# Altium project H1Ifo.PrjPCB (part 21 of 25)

## Sheet IfoEndY2.SchDoc: D1800185
size C; Engineer: Daniel Sigg; DocumentNumber: 6; Revision: 4; SheetNumber: 6; SheetTotal: 8
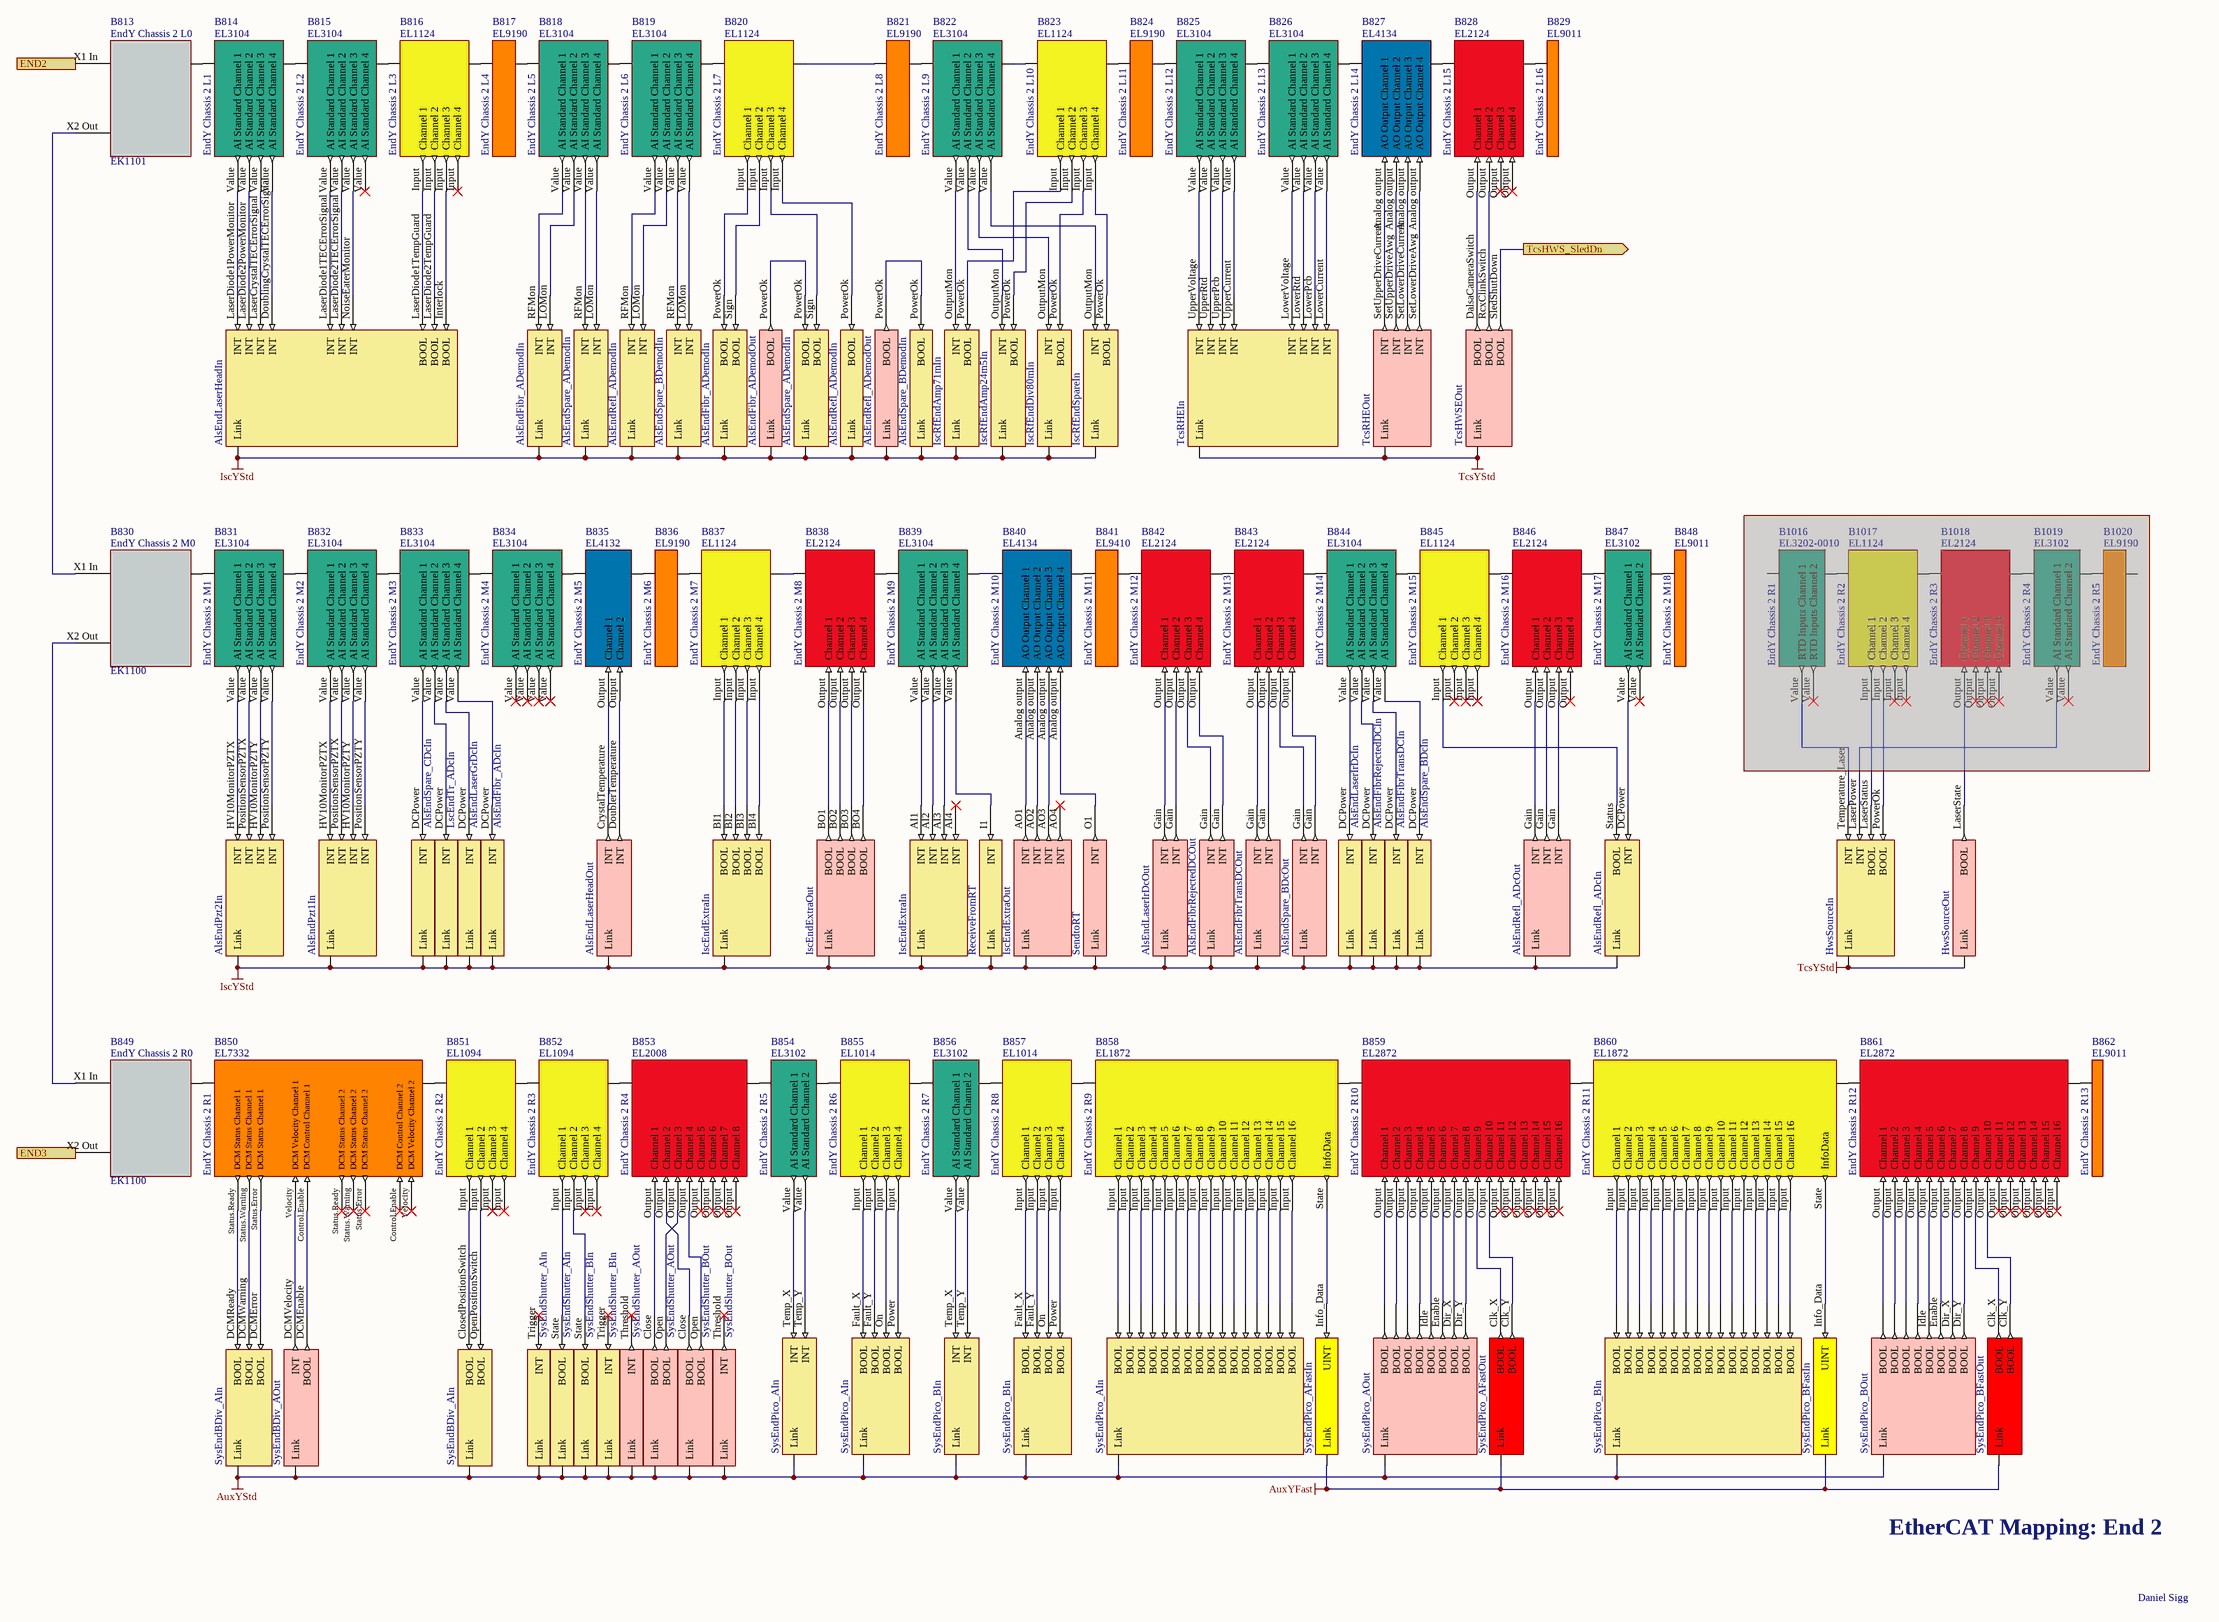
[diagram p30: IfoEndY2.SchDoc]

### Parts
(Parts that share a designator on the sheet are numbered #1, #2 ... from top to bottom, then left to right.)
B813  EndY Chassis 2 L0  Part Number: EK1101
B814  EndY Chassis 2 L1  Part Number: EL3104  (mechanical)
B815  EndY Chassis 2 L2  Part Number: EL3104  (mechanical)
B816  EndY Chassis 2 L3  Part Number: EL1124  (mechanical)
B817  EndY Chassis 2 L4  Part Number: EL9190  (mechanical)
B818  EndY Chassis 2 L5  Part Number: EL3104  (mechanical)
B819  EndY Chassis 2 L6  Part Number: EL3104  (mechanical)
B820  EndY Chassis 2 L7  Part Number: EL1124  (mechanical)
B821  EndY Chassis 2 L8  Part Number: EL9190  (mechanical)
B822  EndY Chassis 2 L9  Part Number: EL3104  (mechanical)
B823  EndY Chassis 2 L10  Part Number: EL1124  (mechanical)
B824  EndY Chassis 2 L11  Part Number: EL9190  (mechanical)
B825  EndY Chassis 2 L12  Part Number: EL3104  (mechanical)
B826  EndY Chassis 2 L13  Part Number: EL3104  (mechanical)
B827  EndY Chassis 2 L14  Part Number: EL4134  (mechanical)
B828  EndY Chassis 2 L15  Part Number: EL2124  (mechanical)
B829  EndY Chassis 2 L16  Part Number: EL9011  (mechanical)
B830  EndY Chassis 2 M0  Part Number: EK1100
B831  EndY Chassis 2 M1  Part Number: EL3104  (mechanical)
B832  EndY Chassis 2 M2  Part Number: EL3104  (mechanical)
B833  EndY Chassis 2 M3  Part Number: EL3104  (mechanical)
B834  EndY Chassis 2 M4  Part Number: EL3104  (mechanical)
B835  EndY Chassis 2 M5  Part Number: EL4132  (mechanical)
B836  EndY Chassis 2 M6  Part Number: EL9190  (mechanical)
B837  EndY Chassis 2 M7  Part Number: EL1124  (mechanical)
B838  EndY Chassis 2 M8  Part Number: EL2124  (mechanical)
B839  EndY Chassis 2 M9  Part Number: EL3104  (mechanical)
B840  EndY Chassis 2 M10  Part Number: EL4134  (mechanical)
B841  EndY Chassis 2 M11  Part Number: EL9410  (mechanical)
B842  EndY Chassis 2 M12  Part Number: EL2124  (mechanical)
B843  EndY Chassis 2 M13  Part Number: EL2124  (mechanical)
B844  EndY Chassis 2 M14  Part Number: EL3104  (mechanical)
B845  EndY Chassis 2 M15  Part Number: EL1124  (mechanical)
B846  EndY Chassis 2 M16  Part Number: EL2124  (mechanical)
B847  EndY Chassis 2 M17  Part Number: EL3102  (mechanical)
B848  EndY Chassis 2 M18  Part Number: EL9011  (mechanical)
B849  EndY Chassis 2 R0  Part Number: EK1100
B850  EndY Chassis 2 R1  Part Number: EL7332  (mechanical)
B851  EndY Chassis 2 R2  Part Number: EL1094  (mechanical)
B852  EndY Chassis 2 R3  Part Number: EL1094  (mechanical)
B853  EndY Chassis 2 R4  Part Number: EL2008  (mechanical)
B854  EndY Chassis 2 R5  Part Number: EL3102  (mechanical)
B855  EndY Chassis 2 R6  Part Number: EL1014  (mechanical)
B856  EndY Chassis 2 R7  Part Number: EL3102  (mechanical)
B857  EndY Chassis 2 R8  Part Number: EL1014  (mechanical)
B858  EndY Chassis 2 R9  Part Number: EL1872  (mechanical)
B859  EndY Chassis 2 R10  Part Number: EL2872  (mechanical)
B860  EndY Chassis 2 R11  Part Number: EL1872  (mechanical)
B861  EndY Chassis 2 R12  Part Number: EL2872  (mechanical)
B862  EndY Chassis 2 R13  Part Number: EL9011  (mechanical)
B1016#1  EndY Chassis 2 R1  Part Number: EL3202-0010  (mechanical)  (masked out: inside a compile mask, not in the netlist)
B1017#1  EndY Chassis 2 R2  Part Number: EL1124  (mechanical)  (masked out: inside a compile mask, not in the netlist)
B1018#1  EndY Chassis 2 R3  Part Number: EL2124  (mechanical)  (masked out: inside a compile mask, not in the netlist)
B1019#1  EndY Chassis 2 R4  Part Number: EL3102  (mechanical)  (masked out: inside a compile mask, not in the netlist)
B1020#1  EndY Chassis 2 R5  Part Number: EL9190  (mechanical)  (masked out: inside a compile mask, not in the netlist)
V477  AlsEndFibr_ADemodIn  (parts A,B of 2)  (no BOM)
V478  AlsEndSpare_ADemodIn  (parts A,B of 2)  (no BOM)
V479  AlsEndRefl_ADemodIn  (parts A,B of 2)  (no BOM)
V480  AlsEndSpare_BDemodIn  (parts A,B of 2)  (no BOM)
V567  SysEndPico_AIn  (parts A,B,C of 3)  (no BOM)
V568  SysEndPico_BIn  (parts A,B,C of 3)  (no BOM)
V633  AlsEndLaserHeadIn  (no BOM)
V634  AlsEndFibr_ADemodOut  (no BOM)
V635  AlsEndRefl_ADemodOut  (no BOM)
V636  IscRfEndAmp71mIn  (no BOM)
V637  IscRfEndAmp24m5In  (no BOM)
V638  IscRfEndDiv80mIn  (no BOM)
V639  IscRfEndSpareIn  (no BOM)
V640  TcsRHEIn  (no BOM)
V641  TcsRHEOut  (no BOM)
V642  TcsHWSEOut  (no BOM)
V643  AlsEndPzt2In  (no BOM)
V644  AlsEndPzt1In  (no BOM)
V645  AlsEndSpare_CDcIn  (no BOM)
V646  LscEndTr_ADcIn  (no BOM)
V647  AlsEndLaserGrDcIn  (no BOM)
V648  AlsEndFibr_ADcIn  (no BOM)
V649  AlsEndLaserHeadOut  (part A of 2)  (no BOM)
V650  IscEndExtraIn  (parts A,B of 2)  (no BOM)
V651  IscEndExtraOut  (parts A,B of 2)  (no BOM)
V652  ReceiveFromRT  (no BOM)
V653  SendtoRT  (no BOM)
V654  AlsEndLaserIrDcOut  (no BOM)
V656  AlsEndFibrRejectedDCOut  (no BOM)
V657  AlsEndFibrTransDCOut  (no BOM)
V658  AlsEndSpare_BDcOut  (no BOM)
V659  AlsEndLaserIrDcIn  (no BOM)
V660  AlsEndFibrRejectedDCIn  (no BOM)
V661  AlsEndFibrTransDCIn  (no BOM)
V662  AlsEndSpare_BDcIn  (no BOM)
V663  AlsEndRefl_ADcOut  (no BOM)
V664  AlsEndRefl_ADcIn  (no BOM)
V665  SysEndPico_AFastIn  (no BOM)
V666  SysEndPico_AOut  (no BOM)
V667  SysEndPico_AFastOut  (no BOM)
V669  SysEndPico_BFastIn  (no BOM)
V670  SysEndPico_BOut  (no BOM)
V671  SysEndPico_BFastOut  (no BOM)
V672  SysEndBDiv_AIn  (parts A,B of 2)  (no BOM)
V673  SysEndBDiv_AOut  (no BOM)
V674  SysEndShutter_AIn  (parts A,B of 2)  (no BOM)
V675  SysEndShutter_BIn  (parts A,B of 2)  (no BOM)
V676  SysEndShutter_AOut  (parts A,B of 2)  (no BOM)
V677  SysEndShutter_BOut  (parts A,B of 2)  (no BOM)
V849  HwsSourceIn  (no BOM)
V867  HwsSourceOut  (no BOM)

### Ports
END2, END3, TcsHWS_SledDn (out)

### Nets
AuxYFast: V665.0(Link) V667.0(Link) V669.0(Link) V671.0(Link)
AuxYStd: V567.0(Link) V567.1(Link) V567.2(Link) V568.0(Link) V568.1(Link) V568.2(Link) V666.0(Link) V670.0(Link) V672.0(Link) V672.1(Link) V673.0(Link) V674.0(Link) V674.1(Link) V675.0(Link) V675.1(Link) V676.0(Link) V676.1(Link) V677.0(Link) V677.1(Link)
IscYStd: V477.0(Link) V477.1(Link) V478.0(Link) V478.1(Link) V479.0(Link) V479.1(Link) V480.0(Link) V480.1(Link) V633.0(Link) V634.?1(Link) V635.?1(Link) V636.?1(Link) V637.?1(Link) V638.?1(Link) V639.?1(Link) V643.0(Link) V644.0(Link) V645.1(Link) V646.1(Link) V647.1(Link) V648.1(Link) V649.0(Link) V650.0(Link) V650.1(Link) V651.0(Link) V651.1(Link) V652.1(Link) V653.0(Link) V654.0(Link) V656.0(Link) V657.0(Link) V658.0(Link) V659.1(Link) V660.1(Link) V661.1(Link) V662.1(Link) V663.0(Link) V664.1(Link)
TcsYStd: V640.0(Link) V641.0(Link) V642.0(Link) V849.1(Link) V867.0(Link)
NetB658_X2 Out: B813.X1_In(A) ; port END2
NetB710_X2 Out: B849.X2_Out(C) ; port END3
NetB738_Output: V642.SledShutDown(BOOL) ; port TcsHWS_SledDn
NetB813_Ebus: B813.Ebus(B) B814.Ebus(A)
NetB813_X2 Out: B813.X2_Out(C) B830.X1_In(A)
NetB814_Ebus: B814.Ebus(B) B815.Ebus(A)
NetB814_Value: B814.Value(AI_Standard_Channel_1) V633.LaserDiode1PowerMonitor(INT)
NetB814_Value: B814.Value(AI_Standard_Channel_2) V633.LaserDiode2PowerMonitor(INT)  [a separate net that carries the same name]
NetB814_Value: B814.Value(AI_Standard_Channel_3) V633.LaserCrystalTECErrorSignal(INT)  [a separate net that carries the same name]
NetB814_Value: B814.Value(AI_Standard_Channel_4) V633.DoublingCrystalTECErrorSignal(INT)  [a separate net that carries the same name]
NetB815_Ebus: B815.Ebus(B) B816.Ebus(A)
NetB815_Value: B815.Value(AI_Standard_Channel_1) V633.LaserDiode1TECErrorSignal(INT)
NetB815_Value: B815.Value(AI_Standard_Channel_2) V633.LaserDiode2TECErrorSignal(INT)  [a separate net that carries the same name]
NetB815_Value: B815.Value(AI_Standard_Channel_3) V633.NoiseEaterMonitor(INT)  [a separate net that carries the same name]
NetB816_Ebus: B816.Ebus(B) B817.Ebus(A)
NetB816_Input: B816.Input(Channel_1) V633.LaserDiode1TempGuard(BOOL)
NetB816_Input: B816.Input(Channel_2) V633.LaserDiode2TempGuard(BOOL)  [a separate net that carries the same name]
NetB816_Input: B816.Input(Channel_3) V633.Interlock(BOOL)  [a separate net that carries the same name]
NetB817_Ebus: B817.Ebus(B) B818.Ebus(A)
NetB818_Ebus: B818.Ebus(B) B819.Ebus(A)
NetB818_Value: B818.Value(AI_Standard_Channel_1) V477.RFMon(INT)
NetB818_Value: B818.Value(AI_Standard_Channel_2) V477.LOMon(INT)  [a separate net that carries the same name]
NetB818_Value: B818.Value(AI_Standard_Channel_3) V478.RFMon(INT)  [a separate net that carries the same name]
NetB818_Value: B818.Value(AI_Standard_Channel_4) V478.LOMon(INT)  [a separate net that carries the same name]
NetB819_Ebus: B819.Ebus(B) B820.Ebus(A)
NetB819_Value: B819.Value(AI_Standard_Channel_1) V479.RFMon(INT)
NetB819_Value: B819.Value(AI_Standard_Channel_2) V479.LOMon(INT)  [a separate net that carries the same name]
NetB819_Value: B819.Value(AI_Standard_Channel_3) V480.RFMon(INT)  [a separate net that carries the same name]
NetB819_Value: B819.Value(AI_Standard_Channel_4) V480.LOMon(INT)  [a separate net that carries the same name]
NetB820_Ebus: B820.Ebus(B) B821.Ebus(A)
NetB820_Input: B820.Input(Channel_1) V477.PowerOk(BOOL)
NetB820_Input: B820.Input(Channel_2) V477.Sign(BOOL)  [a separate net that carries the same name]
NetB820_Input: B820.Input(Channel_3) V478.Sign(BOOL)  [a separate net that carries the same name]
NetB820_Input: B820.Input(Channel_4) V479.PowerOk(BOOL)  [a separate net that carries the same name]
NetB821_Ebus: B821.Ebus(B) B822.Ebus(A)
NetB822_Ebus: B822.Ebus(B) B823.Ebus(A)
NetB822_Value: B822.Value(AI_Standard_Channel_1) V636.OutputMon(INT)
NetB822_Value: B822.Value(AI_Standard_Channel_2) V637.OutputMon(INT)  [a separate net that carries the same name]
NetB822_Value: B822.Value(AI_Standard_Channel_3) V638.OutputMon(INT)  [a separate net that carries the same name]
NetB822_Value: B822.Value(AI_Standard_Channel_4) V639.OutputMon(INT)  [a separate net that carries the same name]
NetB823_Ebus: B823.Ebus(B) B824.Ebus(A)
NetB823_Input: B823.Input(Channel_1) V636.PowerOk(BOOL)
NetB823_Input: B823.Input(Channel_2) V637.PowerOk(BOOL)  [a separate net that carries the same name]
NetB823_Input: B823.Input(Channel_3) V638.PowerOk(BOOL)  [a separate net that carries the same name]
NetB823_Input: B823.Input(Channel_4) V639.PowerOk(BOOL)  [a separate net that carries the same name]
NetB824_Ebus: B824.Ebus(B) B825.Ebus(A)
NetB825_Ebus: B825.Ebus(B) B826.Ebus(A)
NetB825_Value: B825.Value(AI_Standard_Channel_1) V640.UpperVoltage(INT)
NetB825_Value: B825.Value(AI_Standard_Channel_2) V640.UpperRtd(INT)  [a separate net that carries the same name]
NetB825_Value: B825.Value(AI_Standard_Channel_3) V640.UpperPcb(INT)  [a separate net that carries the same name]
NetB825_Value: B825.Value(AI_Standard_Channel_4) V640.UpperCurrent(INT)  [a separate net that carries the same name]
NetB826_Ebus: B826.Ebus(B) B827.Ebus(A)
NetB826_Value: B826.Value(AI_Standard_Channel_1) V640.LowerVoltage(INT)
NetB826_Value: B826.Value(AI_Standard_Channel_2) V640.LowerRtd(INT)  [a separate net that carries the same name]
NetB826_Value: B826.Value(AI_Standard_Channel_3) V640.LowerPcb(INT)  [a separate net that carries the same name]
NetB826_Value: B826.Value(AI_Standard_Channel_4) V640.LowerCurrent(INT)  [a separate net that carries the same name]
NetB827_Analog output: B827.Analog_output(AO_Output_Channel_1) V641.SetUpperDriveCurrent(INT)
NetB827_Analog output: B827.Analog_output(AO_Output_Channel_2) V641.SetUpperDriveAwg(INT)  [a separate net that carries the same name]
NetB827_Analog output: B827.Analog_output(AO_Output_Channel_3) V641.SetLowerDriveCurrent(INT)  [a separate net that carries the same name]
NetB827_Analog output: B827.Analog_output(AO_Output_Channel_4) V641.SetLowerDriveAwg(INT)  [a separate net that carries the same name]
NetB827_Ebus: B827.Ebus(B) B828.Ebus(A)
NetB828_Ebus: B828.Ebus(B) B829.Ebus(A)
NetB828_Output: B828.Output(Channel_1) V642.DalsaCameraSwitch(BOOL)
NetB828_Output: B828.Output(Channel_2) V642.RcxClinkSwitch(BOOL)  [a separate net that carries the same name]
NetB830_Ebus: B830.Ebus(B) B831.Ebus(A)
NetB830_X2 Out: B830.X2_Out(C) B849.X1_In(A)
NetB831_Ebus: B831.Ebus(B) B832.Ebus(A)
NetB831_Value: B831.Value(AI_Standard_Channel_1) V643.HV10MonitorPZTX(INT)
NetB831_Value: B831.Value(AI_Standard_Channel_2) V643.PositionSensorPZTX(INT)  [a separate net that carries the same name]
NetB831_Value: B831.Value(AI_Standard_Channel_3) V643.HV10MonitorPZTY(INT)  [a separate net that carries the same name]
NetB831_Value: B831.Value(AI_Standard_Channel_4) V643.PositionSensorPZTY(INT)  [a separate net that carries the same name]
NetB832_Ebus: B832.Ebus(B) B833.Ebus(A)
NetB832_Value: B832.Value(AI_Standard_Channel_1) V644.HV10MonitorPZTX(INT)
NetB832_Value: B832.Value(AI_Standard_Channel_2) V644.PositionSensorPZTX(INT)  [a separate net that carries the same name]
NetB832_Value: B832.Value(AI_Standard_Channel_3) V644.HV10MonitorPZTY(INT)  [a separate net that carries the same name]
NetB832_Value: B832.Value(AI_Standard_Channel_4) V644.PositionSensorPZTY(INT)  [a separate net that carries the same name]
NetB833_Ebus: B833.Ebus(B) B834.Ebus(A)
NetB833_Value: B833.Value(AI_Standard_Channel_1) V645.DCPower(INT)
NetB833_Value: B833.Value(AI_Standard_Channel_2) V646.DCPower(INT)  [a separate net that carries the same name]
NetB833_Value: B833.Value(AI_Standard_Channel_3) V647.DCPower(INT)  [a separate net that carries the same name]
NetB833_Value: B833.Value(AI_Standard_Channel_4) V648.DCPower(INT)  [a separate net that carries the same name]
NetB834_Ebus: B834.Ebus(B) B835.Ebus(A)
NetB835_Ebus: B835.Ebus(B) B836.Ebus(A)
NetB835_Output: B835.Output(Channel_1) V649.CrystalTemperature(INT)
NetB835_Output: B835.Output(Channel_2) V649.DoublerTemperature(INT)  [a separate net that carries the same name]
NetB836_Ebus: B836.Ebus(B) B837.Ebus(A)
NetB837_Ebus: B837.Ebus(B) B838.Ebus(A)
NetB837_Input: B837.Input(Channel_1) V650.BI1(BOOL)
NetB837_Input: B837.Input(Channel_2) V650.BI2(BOOL)  [a separate net that carries the same name]
NetB837_Input: B837.Input(Channel_3) V650.BI3(BOOL)  [a separate net that carries the same name]
NetB837_Input: B837.Input(Channel_4) V650.BI4(BOOL)  [a separate net that carries the same name]
NetB838_Ebus: B838.Ebus(B) B839.Ebus(A)
NetB838_Output: B838.Output(Channel_1) V651.BO1(BOOL)
NetB838_Output: B838.Output(Channel_2) V651.BO2(BOOL)  [a separate net that carries the same name]
NetB838_Output: B838.Output(Channel_3) V651.BO3(BOOL)  [a separate net that carries the same name]
NetB838_Output: B838.Output(Channel_4) V651.BO4(BOOL)  [a separate net that carries the same name]
NetB839_Ebus: B839.Ebus(B) B840.Ebus(A)
NetB839_Value: B839.Value(AI_Standard_Channel_1) V650.AI1(INT)
NetB839_Value: B839.Value(AI_Standard_Channel_2) V650.AI2(INT)  [a separate net that carries the same name]
NetB839_Value: B839.Value(AI_Standard_Channel_3) V650.AI3(INT)  [a separate net that carries the same name]
NetB839_Value: B839.Value(AI_Standard_Channel_4) V652.I1(INT)  [a separate net that carries the same name]
NetB840_Analog output: B840.Analog_output(AO_Output_Channel_1) V651.AO1(INT)
NetB840_Analog output: B840.Analog_output(AO_Output_Channel_2) V651.AO2(INT)  [a separate net that carries the same name]
NetB840_Analog output: B840.Analog_output(AO_Output_Channel_3) V651.AO3(INT)  [a separate net that carries the same name]
NetB840_Analog output: B840.Analog_output(AO_Output_Channel_4) V653.O1(INT)  [a separate net that carries the same name]
NetB840_Ebus: B840.Ebus(B) B841.Ebus(A)
NetB841_Ebus: B841.Ebus(B) B842.Ebus(A)
NetB842_Ebus: B842.Ebus(B) B843.Ebus(A)
NetB842_Output: B842.Output(Channel_1) V654.Gain(INT)
NetB842_Output: B842.Output(Channel_2) V654.Gain(INT)  [a separate net that carries the same name]
NetB842_Output: B842.Output(Channel_3) V656.Gain(INT)  [a separate net that carries the same name]
NetB842_Output: B842.Output(Channel_4) V656.Gain(INT)  [a separate net that carries the same name]
NetB843_Ebus: B843.Ebus(B) B844.Ebus(A)
NetB843_Output: B843.Output(Channel_1) V657.Gain(INT)
NetB843_Output: B843.Output(Channel_2) V657.Gain(INT)  [a separate net that carries the same name]
NetB843_Output: B843.Output(Channel_3) V658.Gain(INT)  [a separate net that carries the same name]
NetB843_Output: B843.Output(Channel_4) V658.Gain(INT)  [a separate net that carries the same name]
NetB844_Ebus: B844.Ebus(B) B845.Ebus(A)
NetB844_Value: B844.Value(AI_Standard_Channel_1) V659.DCPower(INT)
NetB844_Value: B844.Value(AI_Standard_Channel_2) V660.DCPower(INT)  [a separate net that carries the same name]
NetB844_Value: B844.Value(AI_Standard_Channel_3) V661.DCPower(INT)  [a separate net that carries the same name]
NetB844_Value: B844.Value(AI_Standard_Channel_4) V662.DCPower(INT)  [a separate net that carries the same name]
NetB845_Ebus: B845.Ebus(B) B846.Ebus(A)
NetB845_Input: B845.Input(Channel_1) V664.Status(BOOL)
NetB846_Ebus: B846.Ebus(B) B847.Ebus(A)
NetB846_Output: B846.Output(Channel_1) V663.Gain(INT)
NetB846_Output: B846.Output(Channel_2) V663.Gain(INT)  [a separate net that carries the same name]
NetB846_Output: B846.Output(Channel_3) V663.Gain(INT)  [a separate net that carries the same name]
NetB847_Ebus: B847.Ebus(B) B848.Ebus(A)
NetB847_Value: B847.Value(AI_Standard_Channel_1) V664.DCPower(INT)
NetB849_Ebus: B849.Ebus(B) B850.Ebus(A)
NetB850_Control.Enable: B850.Control.Enable(DCM_Control_Channel_1) V673.DCMEnable(BOOL)
NetB850_Ebus: B850.Ebus(B) B851.Ebus(A)
NetB850_Status.Error: B850.Status.Error(DCM_Status_Channel_1) V672.DCMError(BOOL)
NetB850_Status.Ready: B850.Status.Ready(DCM_Status_Channel_1) V672.DCMReady(BOOL)
NetB850_Status.Warning: B850.Status.Warning(DCM_Status_Channel_1) V672.DCMWarning(BOOL)
NetB850_Velocity: B850.Velocity(DCM_Velocity_Channel_1) V673.DCMVelocity(INT)
NetB851_Ebus: B851.Ebus(B) B852.Ebus(A)
NetB851_Input: B851.Input(Channel_1) V672.ClosedPositionSwitch(BOOL)
NetB851_Input: B851.Input(Channel_2) V672.OpenPositionSwitch(BOOL)  [a separate net that carries the same name]
NetB852_Ebus: B852.Ebus(B) B853.Ebus(A)
NetB852_Input: B852.Input(Channel_1) V674.State(BOOL)
NetB852_Input: B852.Input(Channel_2) V675.State(BOOL)  [a separate net that carries the same name]
NetB853_Ebus: B853.Ebus(B) B854.Ebus(A)
NetB853_Output: B853.Output(Channel_1) V676.Close(BOOL)
NetB853_Output: B853.Output(Channel_2) V677.Close(BOOL)  [a separate net that carries the same name]
NetB853_Output: B853.Output(Channel_3) V676.Open(BOOL)  [a separate net that carries the same name]
NetB853_Output: B853.Output(Channel_4) V677.Open(BOOL)  [a separate net that carries the same name]
NetB854_Ebus: B854.Ebus(B) B855.Ebus(A)
NetB854_Value: B854.Value(AI_Standard_Channel_1) V567.Temp_X(INT)
NetB854_Value: B854.Value(AI_Standard_Channel_2) V567.Temp_Y(INT)  [a separate net that carries the same name]
NetB855_Ebus: B855.Ebus(B) B856.Ebus(A)
NetB855_Input: B855.Input(Channel_1) V567.Fault_X(BOOL)
NetB855_Input: B855.Input(Channel_2) V567.Fault_Y(BOOL)  [a separate net that carries the same name]
NetB855_Input: B855.Input(Channel_3) V567.On(BOOL)  [a separate net that carries the same name]
NetB855_Input: B855.Input(Channel_4) V567.Power(BOOL)  [a separate net that carries the same name]
NetB856_Ebus: B856.Ebus(B) B857.Ebus(A)
NetB856_Value: B856.Value(AI_Standard_Channel_1) V568.Temp_X(INT)
NetB856_Value: B856.Value(AI_Standard_Channel_2) V568.Temp_Y(INT)  [a separate net that carries the same name]
NetB857_Ebus: B857.Ebus(B) B858.Ebus(A)
NetB857_Input: B857.Input(Channel_1) V568.Fault_X(BOOL)
NetB857_Input: B857.Input(Channel_2) V568.Fault_Y(BOOL)  [a separate net that carries the same name]
NetB857_Input: B857.Input(Channel_3) V568.On(BOOL)  [a separate net that carries the same name]
NetB857_Input: B857.Input(Channel_4) V568.Power(BOOL)  [a separate net that carries the same name]
NetB858_Ebus: B858.Ebus(B) B859.Ebus(A)
NetB858_Input: B858.Input(Channel_1) V567.MotorX1(BOOL)
NetB858_Input: B858.Input(Channel_2) V567.MotorX2(BOOL)  [a separate net that carries the same name]
NetB858_Input: B858.Input(Channel_3) V567.MotorX3(BOOL)  [a separate net that carries the same name]
NetB858_Input: B858.Input(Channel_4) V567.MotorX4(BOOL)  [a separate net that carries the same name]
NetB858_Input: B858.Input(Channel_5) V567.MotorX5(BOOL)  [a separate net that carries the same name]
NetB858_Input: B858.Input(Channel_6) V567.MotorX6(BOOL)  [a separate net that carries the same name]
NetB858_Input: B858.Input(Channel_7) V567.MotorX7(BOOL)  [a separate net that carries the same name]
NetB858_Input: B858.Input(Channel_8) V567.MotorX8(BOOL)  [a separate net that carries the same name]
NetB858_Input: B858.Input(Channel_9) V567.MotorY1(BOOL)  [a separate net that carries the same name]
NetB858_Input: B858.Input(Channel_10) V567.MotorY2(BOOL)  [a separate net that carries the same name]
NetB858_Input: B858.Input(Channel_11) V567.MotorY3(BOOL)  [a separate net that carries the same name]
NetB858_Input: B858.Input(Channel_12) V567.MotorY4(BOOL)  [a separate net that carries the same name]
NetB858_Input: B858.Input(Channel_13) V567.MotorY5(BOOL)  [a separate net that carries the same name]
NetB858_Input: B858.Input(Channel_14) V567.MotorY6(BOOL)  [a separate net that carries the same name]
NetB858_Input: B858.Input(Channel_15) V567.MotorY7(BOOL)  [a separate net that carries the same name]
NetB858_Input: B858.Input(Channel_16) V567.MotorY8(BOOL)  [a separate net that carries the same name]
NetB858_State: B858.State(InfoData) V665.Info_Data(UINT)
NetB859_Ebus: B859.Ebus(B) B860.Ebus(A)
NetB859_Output: B859.Output(Channel_1) V666.MOTOR3(BOOL)
NetB859_Output: B859.Output(Channel_2) V666.MOTOR2(BOOL)  [a separate net that carries the same name]
NetB859_Output: B859.Output(Channel_3) V666.MOTOR1(BOOL)  [a separate net that carries the same name]
NetB859_Output: B859.Output(Channel_4) V666.MOTOR4(BOOL)  [a separate net that carries the same name]
NetB859_Output: B859.Output(Channel_5) V666.Idle(BOOL)  [a separate net that carries the same name]
NetB859_Output: B859.Output(Channel_6) V666.Enable(BOOL)  [a separate net that carries the same name]
NetB859_Output: B859.Output(Channel_7) V666.Dir_X(BOOL)  [a separate net that carries the same name]
NetB859_Output: B859.Output(Channel_8) V666.Dir_Y(BOOL)  [a separate net that carries the same name]
NetB859_Output: B859.Output(Channel_9) V667.Clk_X(BOOL)  [a separate net that carries the same name]
NetB859_Output: B859.Output(Channel_10) V667.Clk_Y(BOOL)  [a separate net that carries the same name]
NetB860_Ebus: B860.Ebus(B) B861.Ebus(A)
NetB860_Input: B860.Input(Channel_1) V568.MotorX1(BOOL)
NetB860_Input: B860.Input(Channel_2) V568.MotorX2(BOOL)  [a separate net that carries the same name]
NetB860_Input: B860.Input(Channel_3) V568.MotorX3(BOOL)  [a separate net that carries the same name]
NetB860_Input: B860.Input(Channel_4) V568.MotorX4(BOOL)  [a separate net that carries the same name]
NetB860_Input: B860.Input(Channel_5) V568.MotorX5(BOOL)  [a separate net that carries the same name]
NetB860_Input: B860.Input(Channel_6) V568.MotorX6(BOOL)  [a separate net that carries the same name]
NetB860_Input: B860.Input(Channel_7) V568.MotorX7(BOOL)  [a separate net that carries the same name]
NetB860_Input: B860.Input(Channel_8) V568.MotorX8(BOOL)  [a separate net that carries the same name]
NetB860_Input: B860.Input(Channel_9) V568.MotorY1(BOOL)  [a separate net that carries the same name]
NetB860_Input: B860.Input(Channel_10) V568.MotorY2(BOOL)  [a separate net that carries the same name]
NetB860_Input: B860.Input(Channel_11) V568.MotorY3(BOOL)  [a separate net that carries the same name]
NetB860_Input: B860.Input(Channel_12) V568.MotorY4(BOOL)  [a separate net that carries the same name]
NetB860_Input: B860.Input(Channel_13) V568.MotorY5(BOOL)  [a separate net that carries the same name]
NetB860_Input: B860.Input(Channel_14) V568.MotorY6(BOOL)  [a separate net that carries the same name]
NetB860_Input: B860.Input(Channel_15) V568.MotorY7(BOOL)  [a separate net that carries the same name]
NetB860_Input: B860.Input(Channel_16) V568.MotorY8(BOOL)  [a separate net that carries the same name]
NetB860_State: B860.State(InfoData) V669.Info_Data(UINT)
NetB861_Ebus: B861.Ebus(B) B862.Ebus(A)
NetB861_Output: B861.Output(Channel_1) V670.MOTOR3(BOOL)
NetB861_Output: B861.Output(Channel_2) V670.MOTOR2(BOOL)  [a separate net that carries the same name]
NetB861_Output: B861.Output(Channel_3) V670.MOTOR1(BOOL)  [a separate net that carries the same name]
NetB861_Output: B861.Output(Channel_4) V670.MOTOR4(BOOL)  [a separate net that carries the same name]
NetB861_Output: B861.Output(Channel_5) V670.Idle(BOOL)  [a separate net that carries the same name]
NetB861_Output: B861.Output(Channel_6) V670.Enable(BOOL)  [a separate net that carries the same name]
NetB861_Output: B861.Output(Channel_7) V670.Dir_X(BOOL)  [a separate net that carries the same name]
NetB861_Output: B861.Output(Channel_8) V670.Dir_Y(BOOL)  [a separate net that carries the same name]
NetB861_Output: B861.Output(Channel_9) V671.Clk_X(BOOL)  [a separate net that carries the same name]
NetB861_Output: B861.Output(Channel_10) V671.Clk_Y(BOOL)  [a separate net that carries the same name]
NetV478_PowerOk: V478.PowerOk(BOOL) V634.PowerOk(BOOL)
NetV480_PowerOk: V480.PowerOk(BOOL) V635.PowerOk(BOOL)

Not connected (* = marked no-connect by the designer): B834 Value(AI_Standard_Channel_1)*; V650 AI4(INT)*; V651 AO4(INT)*; V674 Trigger(INT)*; V675 Trigger(INT)*; V676 Threshold(INT)*; V677 Threshold(INT)*; V849 LaserPower(INT) LaserStatus(BOOL) PowerOk(BOOL) Temperature_Laser(INT); V867 LaserState(BOOL)

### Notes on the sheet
- EtherCAT Mapping: End 2
- Daniel Sigg

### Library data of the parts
B813 = CouplerEK1101: EtherCAT Coupler; Rail: Left; BoxNextB: FSICMCHJ; BoxNextC: CBOGYFTA; BoxPrev: DRGVJRDF; PortPrevFull: 1045/C; PortPrevShort: C 'X2 Out'; Fullname: TIID^End Y (EtherCAT)^EndY Link L0 (EK1501-0010)^EndY Link L6 (EK1521)^EndY Chassis 2 L0 (EK1101); BoxPorts: Junction; BoxAddr: 1058; Disabled: False
B814 = TerminalEL3104: EtherCAT Terminal EL3104 4-chn Analog Input; Rail: Left; BoxNextB: AHDTXMGU; BoxPrev: HQGQRHUW; PortPrevFull: 1058/B; PortPrevShort: B; Fullname: TIID^End Y (EtherCAT)^EndY Link L0 (EK1501-0010)^EndY Link L6 (EK1521)^EndY Chassis 2 L0 (EK1101)^EndY Chassis 2 L1 (EL3104); BoxAddr: 1059; Disabled: False
B815 = TerminalEL3104: EtherCAT Terminal EL3104 4-chn Analog Input; Rail: Left; BoxNextB: VJBPGLBS; BoxPrev: FSICMCHJ; PortPrevFull: 1059/B; PortPrevShort: B; Fullname: TIID^End Y (EtherCAT)^EndY Link L0 (EK1501-0010)^EndY Link L6 (EK1521)^EndY Chassis 2 L0 (EK1101)^EndY Chassis 2 L2 (EL3104); BoxAddr: 1060; Disabled: False
B816 = TerminalEL1124: EtherCAT Terminal EL1124 4-chn Digital Input; Rail: Left; BoxNextB: FRVVPRER; BoxPrev: AHDTXMGU; PortPrevFull: 1060/B; PortPrevShort: B; Fullname: TIID^End Y (EtherCAT)^EndY Link L0 (EK1501-0010)^EndY Link L6 (EK1521)^EndY Chassis 2 L0 (EK1101)^EndY Chassis 2 L3 (EL1124); BoxAddr: 1061; Disabled: False
B817 = TerminalEL9190: EtherCAT Terminal EL9190 Supply; BoxType: TerminalPassive; Rail: Left; BoxNextB: HKOEXIQB; BoxPrev: VJBPGLBS; PortPrevShort: B; Fullname: TIID^End Y (EtherCAT)^EndY Link L0 (EK1501-0010)^EndY Link L6 (EK1521)^EndY Chassis 2 L0 (EK1101)^EndY Chassis 2 L4 (EL9190); Disabled: False
B818 = TerminalEL3104: EtherCAT Terminal EL3104 4-chn Analog Input; Rail: Left; BoxNextB: YEMGHAVE; BoxPrev: FRVVPRER; PortPrevFull: 1061/B; PortPrevShort: B; Fullname: TIID^End Y (EtherCAT)^EndY Link L0 (EK1501-0010)^EndY Link L6 (EK1521)^EndY Chassis 2 L0 (EK1101)^EndY Chassis 2 L5 (EL3104); BoxAddr: 1062; Disabled: False
B819 = TerminalEL3104: EtherCAT Terminal EL3104 4-chn Analog Input; Rail: Left; BoxNextB: XWSSFSKL; BoxPrev: HKOEXIQB; PortPrevFull: 1062/B; PortPrevShort: B; Fullname: TIID^End Y (EtherCAT)^EndY Link L0 (EK1501-0010)^EndY Link L6 (EK1521)^EndY Chassis 2 L0 (EK1101)^EndY Chassis 2 L6 (EL3104); BoxAddr: 1063; Disabled: False
B820 = TerminalEL1124: EtherCAT Terminal EL1124 4-chn Digital Input; Rail: Left; BoxNextB: EYTTWDVL; BoxPrev: YEMGHAVE; PortPrevFull: 1063/B; PortPrevShort: B; Fullname: TIID^End Y (EtherCAT)^EndY Link L0 (EK1501-0010)^EndY Link L6 (EK1521)^EndY Chassis 2 L0 (EK1101)^EndY Chassis 2 L7 (EL1124); BoxAddr: 1064; Disabled: False
B821 = TerminalEL9190: EtherCAT Terminal EL9190 Supply; BoxType: TerminalPassive; Rail: Left; BoxNextB: NIRMYMAE; BoxPrev: XWSSFSKL; PortPrevShort: B; Fullname: TIID^End Y (EtherCAT)^EndY Link L0 (EK1501-0010)^EndY Link L6 (EK1521)^EndY Chassis 2 L0 (EK1101)^EndY Chassis 2 L8 (EL9190); Disabled: False
B822 = TerminalEL3104: EtherCAT Terminal EL3104 4-chn Analog Input; Rail: Left; BoxNextB: CRHIJYHI; BoxPrev: EYTTWDVL; PortPrevFull: 1064/B; PortPrevShort: B; Fullname: TIID^End Y (EtherCAT)^EndY Link L0 (EK1501-0010)^EndY Link L6 (EK1521)^EndY Chassis 2 L0 (EK1101)^EndY Chassis 2 L9 (EL3104); BoxAddr: 1065; Disabled: False
B823 = TerminalEL1124: EtherCAT Terminal EL1124 4-chn Digital Input; Rail: Left; BoxNextB: LMAVVUTP; BoxPrev: NIRMYMAE; PortPrevFull: 1065/B; PortPrevShort: B; Fullname: TIID^End Y (EtherCAT)^EndY Link L0 (EK1501-0010)^EndY Link L6 (EK1521)^EndY Chassis 2 L0 (EK1101)^EndY Chassis 2 L10 (EL1124); BoxAddr: 1066; Disabled: False
B824 = TerminalEL9190: EtherCAT Terminal EL9190 Supply; BoxType: TerminalPassive; Rail: Left; BoxNextB: IRQBIVYD; BoxPrev: CRHIJYHI; PortPrevShort: B; Fullname: TIID^End Y (EtherCAT)^EndY Link L0 (EK1501-0010)^EndY Link L6 (EK1521)^EndY Chassis 2 L0 (EK1101)^EndY Chassis 2 L11 (EL9190); Disabled: False
B825 = TerminalEL3104: EtherCAT Terminal EL3104 4-chn Analog Input; Rail: Left; BoxNextB: ROXIEQSX; BoxPrev: LMAVVUTP; PortPrevFull: 1066/B; PortPrevShort: B; Fullname: TIID^End Y (EtherCAT)^EndY Link L0 (EK1501-0010)^EndY Link L6 (EK1521)^EndY Chassis 2 L0 (EK1101)^EndY Chassis 2 L12 (EL3104); BoxAddr: 1067; Disabled: False
B826 = TerminalEL3104: EtherCAT Terminal EL3104 4-chn Analog Input; Rail: Left; BoxNextB: DPRBWEON; BoxPrev: IRQBIVYD; PortPrevFull: 1067/B; PortPrevShort: B; Fullname: TIID^End Y (EtherCAT)^EndY Link L0 (EK1501-0010)^EndY Link L6 (EK1521)^EndY Chassis 2 L0 (EK1101)^EndY Chassis 2 L13 (EL3104); BoxAddr: 1068; Disabled: False
B827 = TerminalEL4134: EtherCAT Terminal EL4134 4-chn Analog Ouput; Rail: Left; BoxNextB: KSJLIDBJ; BoxPrev: ROXIEQSX; PortPrevFull: 1068/B; PortPrevShort: B; Fullname: TIID^End Y (EtherCAT)^EndY Link L0 (EK1501-0010)^EndY Link L6 (EK1521)^EndY Chassis 2 L0 (EK1101)^EndY Chassis 2 L14 (EL4134); BoxAddr: 1069; Disabled: False
B828 = TerminalEL2124: EtherCAT Terminal EL2124 4-chn Digital Ouput; Rail: Left; BoxNextB: KVPNBRWR; BoxPrev: DPRBWEON; PortPrevFull: 1069/B; PortPrevShort: B; Fullname: TIID^End Y (EtherCAT)^EndY Link L0 (EK1501-0010)^EndY Link L6 (EK1521)^EndY Chassis 2 L0 (EK1101)^EndY Chassis 2 L15 (EL2124); BoxAddr: 1070; Disabled: False
B829 = TerminalEL9011: EtherCAT Terminal EL9011 End; BoxType: TerminalPassive; Rail: Left; BoxPrev: KSJLIDBJ; PortPrevShort: B; Fullname: TIID^End Y (EtherCAT)^EndY Link L0 (EK1501-0010)^EndY Link L6 (EK1521)^EndY Chassis 2 L0 (EK1101)^EndY Chassis 2 L16 (EL9011); Disabled: False
B830 = CouplerEK1100: EtherCAT Coupler; Rail: Middle; BoxNextB: ONJUVAXY; BoxNextC: FUNVNSJV; BoxPrev: HQGQRHUW; PortPrevFull: 1058/C; PortPrevShort: C 'X2 Out'; Fullname: TIID^End Y (EtherCAT)^EndY Link L0 (EK1501-0010)^EndY Link L6 (EK1521)^EndY Chassis 2 M0 (EK1100); BoxPorts: Junction; BoxAddr: 1071; Disabled: False
B831 = TerminalEL3104: EtherCAT Terminal EL3104 4-chn Analog Input; Rail: Middle; BoxNextB: HTGOUCWA; BoxPrev: CBOGYFTA; PortPrevFull: 1071/B; PortPrevShort: B; Fullname: TIID^End Y (EtherCAT)^EndY Link L0 (EK1501-0010)^EndY Link L6 (EK1521)^EndY Chassis 2 M0 (EK1100)^EndY Chassis 2 M1 (EL3104); BoxAddr: 1072; Disabled: False
B832 = TerminalEL3104: EtherCAT Terminal EL3104 4-chn Analog Input; Rail: Middle; BoxNextB: WKDUSFXM; BoxPrev: ONJUVAXY; PortPrevFull: 1072/B; PortPrevShort: B; Fullname: TIID^End Y (EtherCAT)^EndY Link L0 (EK1501-0010)^EndY Link L6 (EK1521)^EndY Chassis 2 M0 (EK1100)^EndY Chassis 2 M2 (EL3104); BoxAddr: 1073; Disabled: False
B833 = TerminalEL3104: EtherCAT Terminal EL3104 4-chn Analog Input; Rail: Middle; BoxNextB: TJEHMGBE; BoxPrev: HTGOUCWA; PortPrevFull: 1073/B; PortPrevShort: B; Fullname: TIID^End Y (EtherCAT)^EndY Link L0 (EK1501-0010)^EndY Link L6 (EK1521)^EndY Chassis 2 M0 (EK1100)^EndY Chassis 2 M3 (EL3104); BoxAddr: 1074; Disabled: False
B834 = TerminalEL3104: EtherCAT Terminal EL3104 4-chn Analog Input; Rail: Middle; BoxNextB: CCETHBHM; BoxPrev: WKDUSFXM; PortPrevFull: 1074/B; PortPrevShort: B; Fullname: TIID^End Y (EtherCAT)^EndY Link L0 (EK1501-0010)^EndY Link L6 (EK1521)^EndY Chassis 2 M0 (EK1100)^EndY Chassis 2 M4 (EL3104); BoxAddr: 1075; Disabled: False
B835 = TerminalEL4132: EtherCAT Terminal EL4132 2-chn Analog Ouput; Rail: Middle; BoxNextB: LRYLOUOA; BoxPrev: TJEHMGBE; PortPrevFull: 1075/B; PortPrevShort: B; Fullname: TIID^End Y (EtherCAT)^EndY Link L0 (EK1501-0010)^EndY Link L6 (EK1521)^EndY Chassis 2 M0 (EK1100)^EndY Chassis 2 M5 (EL4132); BoxAddr: 1076; Disabled: False
B836 = TerminalEL9190: EtherCAT Terminal EL9190 Supply; BoxType: TerminalPassive; Rail: Middle; BoxNextB: FLIWLEHG; BoxPrev: CCETHBHM; PortPrevShort: B; Fullname: TIID^End Y (EtherCAT)^EndY Link L0 (EK1501-0010)^EndY Link L6 (EK1521)^EndY Chassis 2 M0 (EK1100)^EndY Chassis 2 M6 (EL9190); Disabled: False
B837 = TerminalEL1124: EtherCAT Terminal EL1124 4-chn Digital Input; Rail: Middle; BoxNextB: BAJJTCFV; BoxPrev: LRYLOUOA; PortPrevFull: 1076/B; PortPrevShort: B; Fullname: TIID^End Y (EtherCAT)^EndY Link L0 (EK1501-0010)^EndY Link L6 (EK1521)^EndY Chassis 2 M0 (EK1100)^EndY Chassis 2 M7 (EL1124); BoxAddr: 1077; Disabled: False
B838 = TerminalEL2124: EtherCAT Terminal EL2124 4-chn Digital Ouput; Rail: Middle; BoxNextB: CXPWVUUE; BoxPrev: FLIWLEHG; PortPrevFull: 1077/B; PortPrevShort: B; Fullname: TIID^End Y (EtherCAT)^EndY Link L0 (EK1501-0010)^EndY Link L6 (EK1521)^EndY Chassis 2 M0 (EK1100)^EndY Chassis 2 M8 (EL2124); BoxAddr: 1078; Disabled: False
B839 = TerminalEL3104: EtherCAT Terminal EL3104 4-chn Analog Input; Rail: Middle; BoxNextB: HDJRKPHO; BoxPrev: BAJJTCFV; PortPrevFull: 1078/B; PortPrevShort: B; Fullname: TIID^End Y (EtherCAT)^EndY Link L0 (EK1501-0010)^EndY Link L6 (EK1521)^EndY Chassis 2 M0 (EK1100)^EndY Chassis 2 M9 (EL3104); BoxAddr: 1079; Disabled: False
B840 = TerminalEL4134: EtherCAT Terminal EL4134 4-chn Analog Ouput; Rail: Middle; BoxNextB: HWDKLRRB; BoxPrev: CXPWVUUE; PortPrevFull: 1079/B; PortPrevShort: B; Fullname: TIID^End Y (EtherCAT)^EndY Link L0 (EK1501-0010)^EndY Link L6 (EK1521)^EndY Chassis 2 M0 (EK1100)^EndY Chassis 2 M10 (EL4134); BoxAddr: 1080; Disabled: False
B841 = TerminalEL9410: EtherCAT Terminal EL9410 Power; Rail: Middle; BoxNextB: JVPLURMX; BoxPrev: HDJRKPHO; PortPrevFull: 1080/B; PortPrevShort: B; Fullname: TIID^End Y (EtherCAT)^EndY Link L0 (EK1501-0010)^EndY Link L6 (EK1521)^EndY Chassis 2 M0 (EK1100)^EndY Chassis 2 M11 (EL9410); BoxAddr: 1081; Disabled: False
B842 = TerminalEL2124: EtherCAT Terminal EL2124 4-chn Digital Ouput; Rail: Middle; BoxNextB: YHWOFDEJ; BoxPrev: HWDKLRRB; PortPrevFull: 1081/B; PortPrevShort: B; Fullname: TIID^End Y (EtherCAT)^EndY Link L0 (EK1501-0010)^EndY Link L6 (EK1521)^EndY Chassis 2 M0 (EK1100)^EndY Chassis 2 M12 (EL2124); BoxAddr: 1082; Disabled: False
B843 = TerminalEL2124: EtherCAT Terminal EL2124 4-chn Digital Ouput; Rail: Middle; BoxNextB: CBIKLIPT; BoxPrev: JVPLURMX; PortPrevFull: 1082/B; PortPrevShort: B; Fullname: TIID^End Y (EtherCAT)^EndY Link L0 (EK1501-0010)^EndY Link L6 (EK1521)^EndY Chassis 2 M0 (EK1100)^EndY Chassis 2 M13 (EL2124); BoxAddr: 1083; Disabled: False
B844 = TerminalEL3104: EtherCAT Terminal EL3104 4-chn Analog Input; Rail: Middle; BoxNextB: UJVYYXJK; BoxPrev: YHWOFDEJ; PortPrevFull: 1083/B; PortPrevShort: B; Fullname: TIID^End Y (EtherCAT)^EndY Link L0 (EK1501-0010)^EndY Link L6 (EK1521)^EndY Chassis 2 M0 (EK1100)^EndY Chassis 2 M14 (EL3104); BoxAddr: 1084; Disabled: False
B845 = TerminalEL1124: EtherCAT Terminal EL1124 4-chn Digital Input; Rail: Middle; BoxNextB: DCUKFVSH; BoxPrev: CBIKLIPT; PortPrevFull: 1084/B; PortPrevShort: B; Fullname: TIID^End Y (EtherCAT)^EndY Link L0 (EK1501-0010)^EndY Link L6 (EK1521)^EndY Chassis 2 M0 (EK1100)^EndY Chassis 2 M15 (EL1124); BoxAddr: 1085; Disabled: False
B846 = TerminalEL2124: EtherCAT Terminal EL2124 4-chn Digital Ouput; Rail: Middle; BoxNextB: NPTWHQSR; BoxPrev: UJVYYXJK; PortPrevFull: 1085/B; PortPrevShort: B; Fullname: TIID^End Y (EtherCAT)^EndY Link L0 (EK1501-0010)^EndY Link L6 (EK1521)^EndY Chassis 2 M0 (EK1100)^EndY Chassis 2 M16 (EL2124); BoxAddr: 1086; Disabled: False
B847 = TerminalEL3102: EtherCAT Terminal EL3102 2-chn Analog Input; Rail: Middle; BoxNextB: EDHVXMSD; BoxPrev: DCUKFVSH; PortPrevFull: 1086/B; PortPrevShort: B; Fullname: TIID^End Y (EtherCAT)^EndY Link L0 (EK1501-0010)^EndY Link L6 (EK1521)^EndY Chassis 2 M0 (EK1100)^EndY Chassis 2 M17 (EL3102); BoxAddr: 1087; Disabled: False
B848 = TerminalEL9011: EtherCAT Terminal EL9011 End; BoxType: TerminalPassive; Rail: Middle; BoxPrev: NPTWHQSR; PortPrevShort: B; Fullname: TIID^End Y (EtherCAT)^EndY Link L0 (EK1501-0010)^EndY Link L6 (EK1521)^EndY Chassis 2 M0 (EK1100)^EndY Chassis 2 M18 (EL9011); Disabled: False
B849 = CouplerEK1100: EtherCAT Coupler; Rail: Right; BoxNextB: BWBVVNJB; BoxNextC: YFCVOVJW; BoxPrev: CBOGYFTA; PortPrevFull: 1071/C; PortPrevShort: C 'X2 Out'; Fullname: TIID^End Y (EtherCAT)^EndY Link L0 (EK1501-0010)^EndY Link L6 (EK1521)^EndY Chassis 2 R0 (EK1100); BoxPorts: Junction; BoxAddr: 1088; Disabled: False
B850 = TerminalEL7332: EtherCAT Terminal EL7332 2-channel DC motor output stage 24 V DC, 1 A; Rail: Right; BoxNextB: FJISIGLS; BoxPrev: FUNVNSJV; PortPrevFull: 1088/B; PortPrevShort: B; Fullname: TIID^End Y (EtherCAT)^EndY Link L0 (EK1501-0010)^EndY Link L6 (EK1521)^EndY Chassis 2 R0 (EK1100)^EndY Chassis 2 R1 (EL7332); BoxAddr: 1089; PDO Outputs: 0x1604,0x1605,0x1606,0x1607; PDO Inputs: 0x1A04,0x1A06; Disabled: False
B851 = TerminalEL1094: EtherCAT Terminal EL1094 4-channel digital input terminal 24 V DC, switching to negative potential; Rail: Right; BoxNextB: BUXVESOL; BoxPrev: BWBVVNJB; PortPrevFull: 1089/B; PortPrevShort: B; Fullname: TIID^End Y (EtherCAT)^EndY Link L0 (EK1501-0010)^EndY Link L6 (EK1521)^EndY Chassis 2 R0 (EK1100)^EndY Chassis 2 R2 (EL1094); BoxAddr: 1090; Disabled: False
B852 = TerminalEL1094: EtherCAT Terminal EL1094 4-channel digital input terminal 24 V DC, switching to negative potential; Rail: Right; BoxNextB: KLAGVHUG; BoxPrev: FJISIGLS; PortPrevFull: 1090/B; PortPrevShort: B; Fullname: TIID^End Y (EtherCAT)^EndY Link L0 (EK1501-0010)^EndY Link L6 (EK1521)^EndY Chassis 2 R0 (EK1100)^EndY Chassis 2 R3 (EL1094); BoxAddr: 1091; Disabled: False
B853 = TerminalEL2008: EtherCAT Terminal EL2008 8-channel digital output terminal 24 V DC, 0.5 A; Rail: Right; BoxNextB: SBAXFODJ; BoxPrev: BUXVESOL; PortPrevFull: 1091/B; PortPrevShort: B; Fullname: TIID^End Y (EtherCAT)^EndY Link L0 (EK1501-0010)^EndY Link L6 (EK1521)^EndY Chassis 2 R0 (EK1100)^EndY Chassis 2 R4 (EL2008); BoxAddr: 1092; Disabled: False
B854 = TerminalEL3102: EtherCAT Terminal EL3102 2-chn Analog Input; Rail: Right; BoxNextB: VRFOCHON; BoxPrev: KLAGVHUG; PortPrevFull: 1092/B; PortPrevShort: B; Fullname: TIID^End Y (EtherCAT)^EndY Link L0 (EK1501-0010)^EndY Link L6 (EK1521)^EndY Chassis 2 R0 (EK1100)^EndY Chassis 2 R5 (EL3102); BoxAddr: 1093; Disabled: False
B855 = TerminalEL1014: EtherCAT Terminal EL1014 4-channel digital input terminal 24 V DC; Rail: Right; BoxNextB: NLDQHFNF; BoxPrev: SBAXFODJ; PortPrevFull: 1093/B; PortPrevShort: B; Fullname: TIID^End Y (EtherCAT)^EndY Link L0 (EK1501-0010)^EndY Link L6 (EK1521)^EndY Chassis 2 R0 (EK1100)^EndY Chassis 2 R6 (EL1014); BoxAddr: 1094; Disabled: False
B856 = TerminalEL3102: EtherCAT Terminal EL3102 2-chn Analog Input; Rail: Right; BoxNextB: GKLEMYXU; BoxPrev: VRFOCHON; PortPrevFull: 1094/B; PortPrevShort: B; Fullname: TIID^End Y (EtherCAT)^EndY Link L0 (EK1501-0010)^EndY Link L6 (EK1521)^EndY Chassis 2 R0 (EK1100)^EndY Chassis 2 R7 (EL3102); BoxAddr: 1095; Disabled: False
B857 = TerminalEL1014: EtherCAT Terminal EL1014 4-channel digital input terminal 24 V DC; Rail: Right; BoxNextB: OGUDFVUD; BoxPrev: NLDQHFNF; PortPrevFull: 1095/B; PortPrevShort: B; Fullname: TIID^End Y (EtherCAT)^EndY Link L0 (EK1501-0010)^EndY Link L6 (EK1521)^EndY Chassis 2 R0 (EK1100)^EndY Chassis 2 R8 (EL1014); BoxAddr: 1096; Disabled: False
B858 = TerminalEL1872InfoData: EtherCAT Terminal EL1872 16-channel digital input terminal 24 V DC; Rail: Right; BoxNextB: URFDELYJ; BoxPrev: GKLEMYXU; PortPrevFull: 1096/B; PortPrevShort: B; Fullname: TIID^End Y (EtherCAT)^EndY Link L0 (EK1501-0010)^EndY Link L6 (EK1521)^EndY Chassis 2 R0 (EK1100)^EndY Chassis 2 R9 (EL1872); BoxAddr: 1097; Disabled: False
B859 = TerminalEL2872: EtherCAT Terminal EL2872 16-channel digital output terminal 24 V DC; Rail: Right; BoxNextB: ODVLFAFK; BoxPrev: OGUDFVUD; PortPrevFull: 1097/B; PortPrevShort: B; Fullname: TIID^End Y (EtherCAT)^EndY Link L0 (EK1501-0010)^EndY Link L6 (EK1521)^EndY Chassis 2 R0 (EK1100)^EndY Chassis 2 R10 (EL2872); BoxAddr: 1098; Disabled: False
B860 = TerminalEL1872InfoData: EtherCAT Terminal EL1872 16-channel digital input terminal 24 V DC; Rail: Right; BoxNextB: YCNMIPMA; BoxPrev: URFDELYJ; PortPrevFull: 1098/B; PortPrevShort: B; Fullname: TIID^End Y (EtherCAT)^EndY Link L0 (EK1501-0010)^EndY Link L6 (EK1521)^EndY Chassis 2 R0 (EK1100)^EndY Chassis 2 R11 (EL1872); BoxAddr: 1099; Disabled: False
B861 = TerminalEL2872: EtherCAT Terminal EL2872 16-channel digital output terminal 24 V DC; Rail: Right; BoxNextB: QVITHHGM; BoxPrev: ODVLFAFK; PortPrevFull: 1099/B; PortPrevShort: B; Fullname: TIID^End Y (EtherCAT)^EndY Link L0 (EK1501-0010)^EndY Link L6 (EK1521)^EndY Chassis 2 R0 (EK1100)^EndY Chassis 2 R12 (EL2872); BoxAddr: 1100; Disabled: False
B862 = TerminalEL9011: EtherCAT Terminal EL9011 End; BoxType: TerminalPassive; Rail: Right; BoxPrev: YCNMIPMA; PortPrevShort: B; Fullname: TIID^End Y (EtherCAT)^EndY Link L0 (EK1501-0010)^EndY Link L6 (EK1521)^EndY Chassis 2 R0 (EK1100)^EndY Chassis 2 R13 (EL9011); Disabled: False
B1016#1 = TerminalEL3202-0010: EtherCAT Terminal EL3202-0010 2-chn Temperature Input; Disabled: False
B1017#1 = TerminalEL1124: EtherCAT Terminal EL1124 4-chn Digital Input; Disabled: False
B1018#1 = TerminalEL2124: EtherCAT Terminal EL2124 4-chn Digital Ouput; Disabled: False
B1019#1 = TerminalEL3102: EtherCAT Terminal EL3102 2-chn Analog Input; Disabled: False
B1020#1 = TerminalEL9190: EtherCAT Terminal EL9190 Supply; BoxType: TerminalPassive; Rail: Left; Disabled: False
V477 V478 = Demodulator_DemodulatorInStructSign: DemodulatorInStruct; BoxType: Variable; Instance: H1IscEndY Instance; PLC: H1IscEndY; Task: IscEStd
V479 V480 = Demodulator_DemodulatorInStructOk: DemodulatorInStruct; BoxType: Variable; Instance: H1IscEndY Instance; PLC: H1IscEndY; Task: IscEStd
V567 V568 = Picomotor_PicomotorInStruct: PicomotorInStruct; BoxType: Variable; Instance: H1AuxEndY Instance; PLC: H1AuxEndY; Task: AuxEStd
V633 = ALSLaser_ALSLaserInStruct: ALSLaserInStruct; BoxType: Variable; Instance: H1IscEndY Instance; PLC: H1IscEndY; Task: IscEStd
V634 V635 = Demodulator_DemodulatorOutStruct: DemodulatorOutStruct; BoxType: Variable; Instance: H1IscEndY Instance; PLC: H1IscEndY; Task: IscEStd
V636-V639 = RFAmplifier_RFAmplifierInStruct: RFAmplifierInStruct; BoxType: Variable; Instance: H1IscEndY Instance; PLC: H1IscEndY; Task: IscEStd
V640 = RingHeater_RingHeaterInStruct: RingHeaterInStruct; BoxType: Variable; Instance: H1TcsEndY Instance; PLC: H1TcsEndY; Task: TcsEStd
V641 = RingHeater_RingHeaterOutStruct: RingHeaterOutStruct; BoxType: Variable; Instance: H1TcsEndY Instance; PLC: H1TcsEndY; Task: TcsEStd
V642 = HartmannSensor_HartmannSensorEndOutStruct: HartmannSensorOutStruct; BoxType: Variable; Instance: H1TcsEndY Instance; PLC: H1TcsEndY; Task: TcsEStd
V643 V644 = PZTMirror_PZTMirrorInStruct: PZTMirrorInStruct; BoxType: Variable; Instance: H1IscEndY Instance; PLC: H1IscEndY; Task: IscEStd
V645-V648 V659-V662 = DCPower_DCPowerInStruct: DCPowerInStruct; BoxType: Variable; Instance: H1IscEndY Instance; PLC: H1IscEndY; Task: IscEStd
V649 = ALSLaser_ALSLaserOutStruct: ALSLaserOutStruct; BoxType: Variable; Instance: H1IscEndY Instance; PLC: H1IscEndY; Task: IscEStd
V650 = Auxiliary_AuxiliaryInStruct: AuxiliaryInStruct; BoxType: Variable; Instance: H1IscEndY Instance; PLC: H1IscEndY; Task: IscEStd
V651 = Auxiliary_AuxiliaryOutStruct: AuxiliaryOutStruct; BoxType: Variable; Instance: H1IscEndY Instance; PLC: H1IscEndY; Task: IscEStd
V652 = RTCommunication_ReceiveFromRtInStruct: ReceiveFromRtInStruct; BoxType: Variable; Instance: H1IscEndY Instance; PLC: H1IscEndY; Task: IscEStd
V653 = RTCommunication_SendToRtOutStruct: SendToRtOutStruct; BoxType: Variable; Instance: H1IscEndY Instance; PLC: H1IscEndY; Task: IscEStd
V654 V656-V658 = DCPower_DCPowerOutStruct: DCPowerOutStruct; BoxType: Variable; Instance: H1IscEndY Instance; PLC: H1IscEndY; Task: IscEStd
V663 = DCPower_DCPowerOutStructLegacy: DCPowerOutStruct; BoxType: Variable; Instance: H1IscEndY Instance; PLC: H1IscEndY; Task: IscEStd
V664 = DCPower_DCPowerInStructLegacy: DCPowerInStruct; BoxType: Variable; Instance: H1IscEndY Instance; PLC: H1IscEndY; Task: IscEStd
V665 V669 = Picomotor_PicomotorFastInStruct: PicomotorFastInStruct; BoxType: Variable; Instance: H1AuxEndY Instance; PLC: H1AuxEndY; Task: AuxEFast
V666 V670 = Picomotor_PicomotorOutStruct: PicomotorOutStruct; BoxType: Variable; Instance: H1AuxEndY Instance; PLC: H1AuxEndY; Task: AuxEStd
V667 V671 = Picomotor_PicomotorFastOutStruct: PicomotorFastOutStruct; BoxType: Variable; Instance: H1AuxEndY Instance; PLC: H1AuxEndY; Task: AuxEFast
V672 = BeamDiverter_BeamDiverterInStruct: BeamDiverterInStruct; BoxType: Variable; Instance: H1AuxEndY Instance; PLC: H1AuxEndY; Task: AuxEStd
V673 = BeamDiverter_BeamDiverterOutStruct: BeamDiverterOutStruct; BoxType: Variable; Instance: H1AuxEndY Instance; PLC: H1AuxEndY; Task: AuxEStd
V674 V675 = ShutterControl_ShutterControlInStruct: ShutterControlInStruct; BoxType: Variable; Instance: H1AuxEndY Instance; PLC: H1AuxEndY; Task: AuxEStd
V676 V677 = ShutterControl_ShutterControlOutStruct: ShutterControlOutStruct; BoxType: Variable; Instance: H1AuxEndY Instance; PLC: H1AuxEndY; Task: AuxEStd
V849 = HartmannSource_HartmannSourceEndInStruct: HartmannSourceEndInStruct; BoxType: Variable; Instance: H1TcsEndY Instance; PLC: H1TcsEndY; Task: TcsEStd
V867 = HartmannSource_HartmannSourceEndOutStruct: HartmannSourceEndOutStruct; BoxType: Variable; Task: TcsEStd; PLC: H1TcsEndY; Instance: H1TcsEndY Instance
